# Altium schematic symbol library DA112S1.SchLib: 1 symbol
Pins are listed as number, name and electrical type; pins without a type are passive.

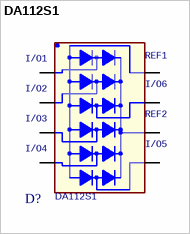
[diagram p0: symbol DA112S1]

## DA112S1
designator D?
footprint ST_SO8
pins: 1 I/O1, 2 I/O2, 3 I/O3, 4 I/O4, 5 I/O5, 6 REF2, 7 I/O6, 8 REF1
